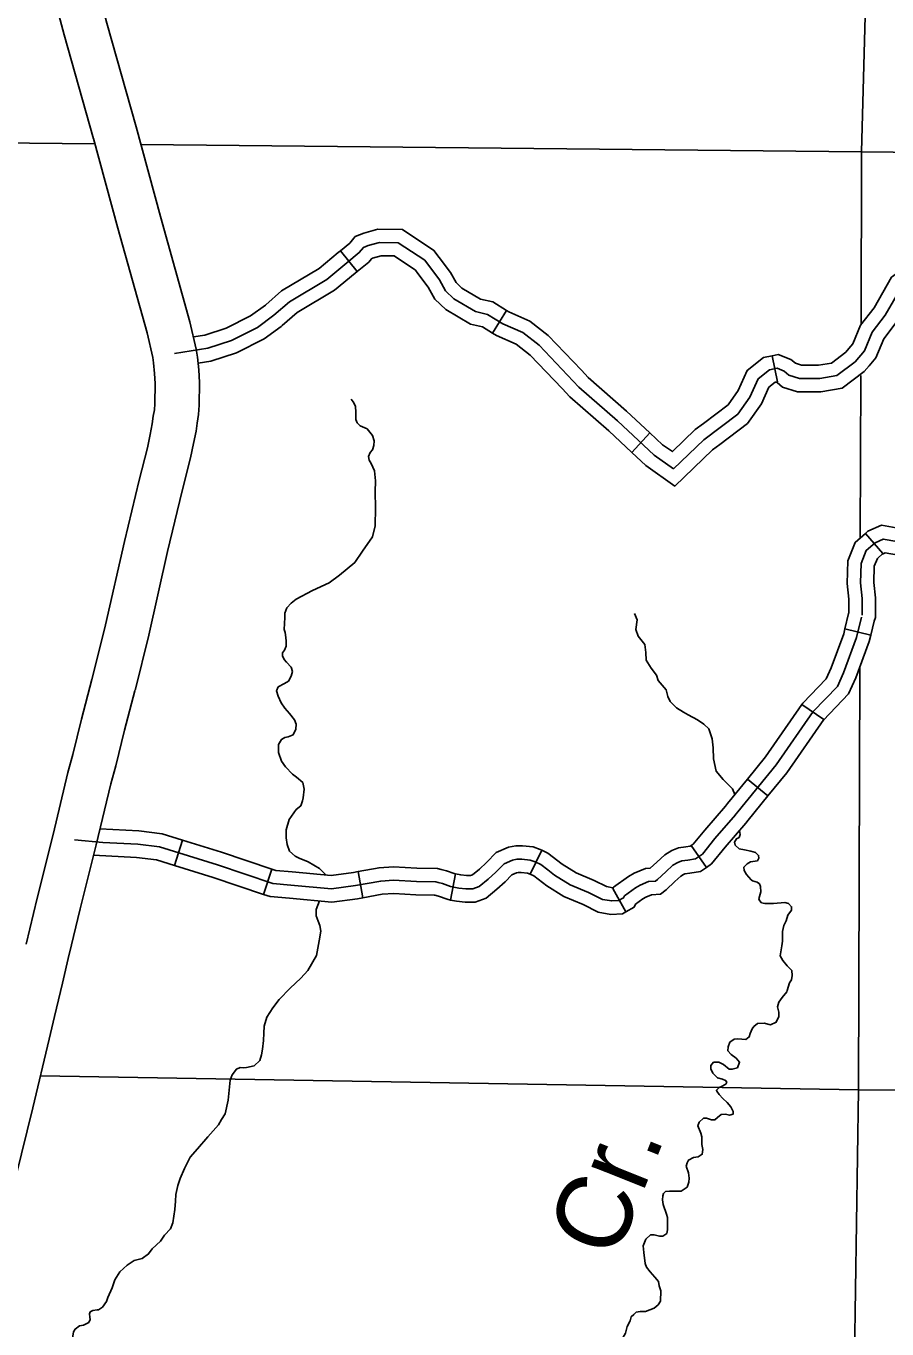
# Model space of a CAD drawing. Extents: x 8749 to 11879, y 13275 to 15339.
# Drawn here: x 10331.7 to 10428.7, y 14052.6 to 14199.4 of the extents above; entities that cross this region are included whole.
import ezdxf

# ---------------------------------------------------------------- set-up
doc = ezdxf.new("R2010")
doc.units = 0
for name, color, linetype in [('Level 10', 7, 'Continuous'), ('Level 31', 7, 'Continuous'), ('Level 32', 7, 'Continuous'), ('Level 35', 7, 'Continuous'), ('Level 45', 7, 'Continuous'), ('Level 5', 7, 'Continuous')]:
    doc.layers.add(name, color=color, linetype=linetype)

msp = doc.modelspace()

# ---------------------------------------------------------------- linework, layer by layer
at = {"layer": 'Level 10'}
msp.add_line((10344.08, 14188.03), (10344.08, 14188.05), dxfattribs=at)
for points in [[(10344.08, 14188.05), (10340.79, 14199.71), (10338.28, 14209.16), (10335.38, 14217.79), (10332.16, 14227.56)], [(10327.41, 14225.99), (10330.64, 14216.21), (10333.49, 14207.73), (10335.96, 14198.39), (10339.26, 14186.69)], [(10351.12, 14155.6), (10351.17, 14156.65), (10351.23, 14159.22), (10351.14, 14160.66), (10350.99, 14162.06), (10350.86, 14162.97), (10350.14, 14166.05), (10346.84, 14177.94), (10344.08, 14188.03)], [(10339.26, 14186.71), (10342.02, 14176.61), (10345.3, 14164.81), (10345.94, 14162.04), (10346.03, 14161.45), (10346.15, 14160.25), (10346.22, 14159.12), (10346.17, 14156.82), (10346.14, 14156.15)], [(10346.14, 14156.15), (10346.01, 14155.42), (10345.9, 14154.58), (10345.65, 14153.35), (10345.34, 14151.85), (10344.42, 14148.22), (10342.75, 14141.32), (10340.63, 14131.91), (10339.09, 14125.72)], [(10343.95, 14124.52), (10345.49, 14130.76), (10347.62, 14140.18), (10349.28, 14147.02), (10350.21, 14150.74), (10350.54, 14152.35), (10350.83, 14153.74), (10350.95, 14154.65), (10351.12, 14155.6)], [(10339.1, 14125.75), (10337.93, 14121.29), (10336.93, 14117.31), (10336.37, 14115.26), (10334.71, 14108.29), (10332.92, 14101.11), (10331.67, 14095.93)], [(10336.53, 14094.76), (10337.77, 14099.92), (10339.57, 14107.11), (10341.21, 14114.01), (10341.77, 14116.03), (10342.78, 14120.05), (10343.94, 14124.49)], [(10323.8, 14042.22), (10325.15, 14048.05), (10326.75, 14054.38), (10328.56, 14061.5), (10329.05, 14063.5), (10330.13, 14068.11), (10330.53, 14069.71), (10332.43, 14077.47), (10334.26, 14085.21), (10334.89, 14087.78), (10335.79, 14091.54), (10336.54, 14094.78)]]:
    msp.add_lwpolyline(points, dxfattribs=at)
at = {"layer": 'Level 31'}
for points in [[(10431.13, 14141.08), (10428.29, 14141.58), (10427.38, 14141.17), (10426.37, 14140.3), (10425.78, 14138.83), (10425.73, 14136.63), (10425.91, 14134.89), (10425.9, 14133)], [(10425.82, 14132.76), (10425.27, 14130.47), (10423.81, 14126.5), (10423.12, 14124.97), (10420.37, 14122.13), (10416.22, 14116.14), (10411.89, 14110.83), (10411.53, 14110.38)], [(10411.64, 14110.51), (10409.31, 14107.82), (10407.9, 14106.08), (10407.12, 14105.54), (10406.25, 14105.4), (10405.57, 14105.31), (10405.12, 14105.14), (10404.57, 14104.81), (10403.79, 14104.07), (10402.83, 14103.21), (10402.6, 14103.02), (10401.83, 14102.98), (10400.87, 14102.57), (10400.37, 14102.29), (10399.11, 14101.37), (10399.02, 14101.14), (10398.45, 14100.83), (10397.68, 14100.79), (10396.63, 14100.97), (10395.07, 14101.75), (10392.98, 14102.61), (10391.24, 14103.71), (10390.47, 14104.3), (10389.69, 14104.9), (10389.05, 14105.22), (10388.5, 14105.4), (10387.55, 14105.49), (10387, 14105.49), (10386.5, 14105.4), (10385.54, 14104.99), (10384.63, 14104.03), (10383.76, 14103.25), (10382.75, 14102.43), (10382.02, 14102.16), (10381.25, 14102.16), (10380.43, 14102.25), (10379.51, 14102.43), (10378.6, 14102.75), (10378.1, 14102.89)], [(10378.1, 14102.89), (10377.86, 14102.95), (10375.66, 14102.99), (10373.1, 14103.13), (10371.64, 14103.04), (10368.8, 14102.53), (10366.1, 14102.17), (10361.52, 14102.58), (10359.5, 14102.76), (10353.23, 14104.87), (10346.69, 14106.89), (10344.26, 14107.21), (10340.32, 14107.39), (10337.14, 14107.7)]]:
    msp.add_lwpolyline(points, dxfattribs=at)
at = {"layer": 'Level 32'}
for p, q in [((10426.29, 14142.21), (10428.25, 14139.94)), ((10423.97, 14131.46), (10426.89, 14130.76)), ((10419.12, 14122.95), (10421.58, 14121.24)), ((10412.97, 14114.52), (10415.29, 14112.63)), ((10349.3, 14107.65), (10348.41, 14104.79)), ((10389.82, 14106.51), (10388.48, 14103.82)), ((10406.64, 14107.04), (10408.37, 14104.58)), ((10359.38, 14104.39), (10358.42, 14101.54)), ((10369.11, 14104.11), (10369.63, 14101.16)), ((10380.09, 14103.84), (10379.5, 14100.9)), ((10397.82, 14102.2), (10399.26, 14099.57))]:
    msp.add_line(p, q, dxfattribs=at)
for points in [[(10437.69, 14141.8), (10434.69, 14141.97), (10431.39, 14142.55), (10428.1, 14143.14), (10426.56, 14142.45), (10426.29, 14142.21)], [(10426.29, 14142.21), (10425.12, 14141.2), (10424.28, 14139.14), (10424.23, 14136.57), (10424.41, 14134.81), (10424.41, 14133.25), (10424.38, 14133.18), (10423.97, 14131.46)], [(10437.52, 14138.8), (10434.35, 14138.99), (10430.87, 14139.6), (10428.49, 14140.02), (10428.19, 14139.89), (10428.25, 14139.94)], [(10428.25, 14139.94), (10427.63, 14139.4), (10427.27, 14138.52), (10427.23, 14136.69), (10427.41, 14134.96), (10427.4, 14132.74), (10427.26, 14132.34), (10426.89, 14130.76)], [(10423.97, 14131.46), (10423.84, 14130.9), (10422.42, 14127.07), (10421.86, 14125.82), (10419.21, 14123.08), (10419.12, 14122.95)], [(10426.89, 14130.76), (10426.71, 14130.03), (10425.2, 14125.94), (10424.38, 14124.12), (10421.54, 14121.17), (10421.59, 14121.24)], [(10419.12, 14122.95), (10415.02, 14117.05), (10412.97, 14114.52)], [(10421.58, 14121.24), (10417.42, 14115.24), (10415.29, 14112.63)], [(10412.97, 14114.52), (10410.73, 14111.78), (10410.49, 14111.48), (10408.16, 14108.78), (10406.86, 14107.19), (10406.64, 14107.04)], [(10415.29, 14112.63), (10413.06, 14109.89), (10412.79, 14109.55), (10410.46, 14106.86), (10408.93, 14104.98), (10408.37, 14104.58)], [(10349.3, 14107.65), (10347.01, 14108.36), (10344.39, 14108.7), (10340, 14108.91)], [(10359.38, 14104.39), (10353.69, 14106.3), (10349.3, 14107.65)], [(10389.82, 14106.51), (10389.63, 14106.61), (10388.82, 14106.88), (10387.62, 14106.99), (10386.86, 14106.99), (10386.06, 14106.84), (10384.66, 14106.25), (10383.58, 14105.11), (10382.78, 14104.39), (10382, 14103.75), (10381.75, 14103.66), (10381.33, 14103.66), (10380.66, 14103.73), (10380.09, 14103.84)], [(10397.82, 14102.28), (10397.1, 14102.41), (10395.7, 14103.11), (10393.67, 14103.95), (10392.1, 14104.94), (10390.49, 14106.17), (10389.82, 14106.51)], [(10406.64, 14107.04), (10406.54, 14106.96), (10406.04, 14106.88), (10405.2, 14106.77), (10404.47, 14106.49), (10403.66, 14106.01), (10402.77, 14105.18), (10402.02, 14104.49), (10401.48, 14104.46), (10400.21, 14103.92), (10399.56, 14103.56), (10397.88, 14102.33), (10397.83, 14102.2), (10397.82, 14102.2)], [(10348.41, 14104.79), (10346.37, 14105.42), (10344.13, 14105.71), (10339.28, 14105.94)], [(10358.42, 14101.54), (10352.77, 14103.44), (10348.41, 14104.79)], [(10369.11, 14104.11), (10368.57, 14104.02), (10366.06, 14103.68), (10361.65, 14104.07), (10359.82, 14104.24), (10359.38, 14104.39)], [(10380.09, 14103.84), (10379.91, 14103.88), (10379.05, 14104.18), (10378.47, 14104.34), (10378.05, 14104.44), (10375.72, 14104.49), (10373.09, 14104.63), (10371.46, 14104.53), (10369.11, 14104.11)], [(10388.48, 14103.82), (10388.48, 14103.83), (10388.19, 14103.92), (10387.47, 14103.99), (10387.13, 14103.99), (10386.93, 14103.95), (10386.41, 14103.73), (10385.67, 14102.95), (10384.73, 14102.11), (10383.51, 14101.11), (10382.3, 14100.66), (10381.17, 14100.66), (10380.2, 14100.76), (10379.5, 14100.9)], [(10399.26, 14099.57), (10398.88, 14099.35), (10397.59, 14099.28), (10396.15, 14099.53), (10394.45, 14100.38), (10392.28, 14101.28), (10390.38, 14102.48), (10388.89, 14103.62), (10388.48, 14103.82)], [(10408.37, 14104.58), (10407.7, 14104.11), (10406.47, 14103.91), (10405.94, 14103.84), (10405.78, 14103.78), (10405.47, 14103.6), (10404.81, 14102.97), (10403.8, 14102.06), (10403.17, 14101.55), (10402.18, 14101.5), (10401.53, 14101.22), (10401.17, 14101.02), (10400.35, 14100.42), (10400.21, 14100.09), (10399.26, 14099.57)], [(10369.63, 14101.16), (10369.03, 14101.05), (10366.13, 14100.66), (10361.38, 14101.09), (10359.19, 14101.29), (10358.42, 14101.54)], [(10379.5, 14100.9), (10379.12, 14100.98), (10378.15, 14101.32), (10377.73, 14101.44), (10377.67, 14101.45), (10375.61, 14101.49), (10373.11, 14101.63), (10371.81, 14101.55), (10369.63, 14101.16)]]:
    msp.add_lwpolyline(points, dxfattribs=at)
at = {"layer": 'Level 35'}
for points in [[(10370.11, 14153.99), (10369.33, 14154.34), (10368.97, 14154.67), (10368.82, 14155.05), (10368.82, 14155.84), (10368.79, 14156.55), (10368.52, 14157.06), (10368.31, 14157.36)], [(10370.93, 14149.25), (10370.57, 14150.1), (10370.34, 14150.48), (10370.27, 14150.89), (10370.47, 14151.32), (10370.72, 14151.62), (10370.88, 14152.13), (10370.9, 14152.64), (10370.7, 14153.25), (10370.11, 14153.99)], [(10368.72, 14138.92), (10369.58, 14140.21), (10370.7, 14141.84), (10371, 14143.06), (10371.05, 14145.09), (10371.03, 14146.89), (10371.05, 14148.16), (10370.93, 14149.25)], [(10362.12, 14134.79), (10363.95, 14135.79), (10365.83, 14136.63), (10366.99, 14137.52), (10368.72, 14138.92)], [(10360.07, 14124.94), (10360.78, 14125.29), (10361.23, 14125.57), (10361.54, 14126.11), (10361.69, 14126.66), (10361.56, 14127.15), (10361.03, 14127.71), (10360.75, 14128.01), (10360.57, 14128.42), (10360.57, 14128.75), (10360.8, 14129.05), (10360.98, 14129.51), (10360.98, 14130.09), (10360.93, 14130.47), (10360.88, 14131.03), (10360.75, 14131.39), (10360.78, 14132.07), (10360.85, 14132.73), (10360.83, 14133.22), (10361.05, 14133.83), (10361.56, 14134.36), (10362.12, 14134.79)], [(10405.77, 14122.08), (10405, 14122.56), (10404.25, 14123.26), (10404.02, 14123.84), (10403.8, 14124.59), (10403.35, 14125.11), (10402.92, 14125.64), (10402.72, 14126.24), (10402.13, 14127.04), (10401.58, 14127.94), (10401.53, 14128.81), (10401.4, 14129.71), (10400.68, 14130.64), (10400.4, 14131.38), (10400.53, 14132.48), (10400.25, 14133.18)], [(10360.14, 14118.43), (10360.45, 14119), (10360.83, 14119.2), (10361.21, 14119.28), (10361.77, 14119.53), (10362.07, 14120.14), (10362.1, 14120.7), (10361.94, 14121.19), (10361.38, 14121.92), (10360.85, 14122.53), (10360.42, 14123.12), (10360.07, 14123.88), (10359.91, 14124.46), (10360.07, 14124.94)], [(10411.28, 14113.44), (10410.23, 14114.48), (10409.44, 14115.43), (10409.14, 14116.8), (10409.11, 14118.05), (10409.01, 14119.05), (10408.64, 14120.18), (10408.06, 14120.73), (10407.36, 14121.2), (10406.31, 14121.78), (10405.77, 14122.08)], [(10364.76, 14104.44), (10363.47, 14105.22), (10362.45, 14105.61), (10361.99, 14105.86), (10361.38, 14106.42), (10361.08, 14107.16), (10361, 14107.92), (10360.98, 14108.81), (10361.33, 14109.97), (10362.12, 14111.12), (10362.65, 14111.52), (10362.83, 14112.06), (10362.91, 14112.41), (10363.03, 14113.4), (10362.88, 14114.14), (10362.15, 14114.75), (10361.71, 14115.1), (10360.9, 14115.92), (10360.45, 14116.53), (10360.14, 14117.52), (10360.14, 14118.43)], [(10411.57, 14112.81), (10411.28, 14113.44)], [(10413.38, 14103.16), (10412.88, 14103.77), (10412.61, 14104.22), (10412.56, 14104.6), (10412.93, 14104.97), (10413.33, 14105.2), (10414.1, 14105.3), (10414.28, 14105.62), (10414.23, 14105.92), (10413.9, 14106.25), (10413.36, 14106.42), (10412.66, 14106.55), (10412.03, 14106.67), (10411.61, 14107.1), (10411.51, 14107.42), (10411.76, 14107.8), (10412.03, 14107.95), (10412.16, 14108.3), (10412.09, 14108.75)], [(10365.46, 14103.73), (10364.76, 14104.44)], [(10416.93, 14096.27), (10416.93, 14097.36), (10417.08, 14098.01), (10417.35, 14098.56), (10417.52, 14099.21), (10417.95, 14099.76), (10417.95, 14100.14), (10417.62, 14100.49), (10417.18, 14100.61), (10415.93, 14100.51), (10415.43, 14100.49), (10414.95, 14100.51), (10414.58, 14100.59), (10414.33, 14100.84), (10414.28, 14101.04), (10414.48, 14101.81), (10414.45, 14102.41), (10414.35, 14102.71), (10414.08, 14102.93), (10413.55, 14103.08), (10413.38, 14103.16)], [(10360.2, 14089.69), (10361.44, 14090.95), (10362.63, 14092.09), (10363.44, 14092.95), (10364.4, 14094.63), (10364.71, 14096.31), (10364.91, 14097.4), (10364.79, 14098.03), (10364.58, 14098.52), (10364.35, 14099.13), (10364.35, 14099.84), (10364.73, 14100.79)], [(10410.99, 14084.87), (10411.48, 14085.2), (10411.91, 14085.25), (10412.78, 14085.18), (10413.18, 14085.48), (10413.28, 14085.85), (10413.5, 14086.4), (10413.68, 14086.63), (10414.13, 14086.98), (10414.88, 14087.03), (10415.58, 14086.83), (10416.23, 14087.13), (10416.5, 14087.78), (10416.53, 14088.25), (10416.38, 14088.88), (10416.53, 14089.4), (10416.9, 14089.9), (10417.42, 14090.57), (10417.47, 14090.7), (10417.72, 14091.55), (10417.95, 14091.92), (10418.02, 14092.4), (10418, 14092.95), (10417.45, 14093.5), (10416.95, 14094.1), (10416.68, 14094.62), (10416.85, 14095.75), (10416.93, 14096.27)], [(10356.52, 14082.01), (10357.38, 14082.22), (10358.01, 14082.83), (10358.22, 14083.47), (10358.32, 14084.1), (10358.42, 14085.07), (10358.45, 14085.88), (10358.5, 14086.67), (10358.8, 14087.7), (10359.49, 14088.75), (10360.2, 14089.69)], [(10407.72, 14074.62), (10407.39, 14075.45), (10407.52, 14075.87), (10408.04, 14076.3), (10408.37, 14076.3), (10408.94, 14076.12), (10409.29, 14076.12), (10409.62, 14076.4), (10410.01, 14076.72), (10410.51, 14076.75), (10410.96, 14076.65), (10411.36, 14076.77), (10411.36, 14077.05), (10411.09, 14077.6), (10410.69, 14078.07), (10410.19, 14078.55), (10409.79, 14078.97), (10409.52, 14079.37), (10409.49, 14079.47), (10409.79, 14079.77), (10410.04, 14079.87), (10410.54, 14080.15), (10410.64, 14080.37), (10410.51, 14080.55), (10410.16, 14080.7), (10409.62, 14080.85), (10409.09, 14081.37), (10408.84, 14081.87), (10408.84, 14082.25), (10409.17, 14082.62), (10409.76, 14082.62), (10410.29, 14082.37), (10410.91, 14081.85), (10411.26, 14081.82), (10411.84, 14082), (10412.09, 14082.62), (10411.69, 14083.09), (10411.16, 14083.49), (10410.76, 14083.92), (10410.79, 14084.34), (10410.99, 14084.87)], [(10349.52, 14070.65), (10350.17, 14071.92), (10351.01, 14072.86), (10352.15, 14074.21), (10353.37, 14075.58), (10353.7, 14076.17), (10354.11, 14076.8), (10354.44, 14078.35), (10354.56, 14079.47), (10354.69, 14080.61), (10354.89, 14081.2), (10355.38, 14081.83), (10355.81, 14082.01), (10356.19, 14081.98), (10356.52, 14082.01)], [(10403.87, 14065.48), (10403.47, 14066.6), (10403.42, 14067.12), (10403.45, 14067.55), (10403.52, 14067.82), (10403.75, 14068.05), (10404.2, 14068.1), (10404.87, 14068.1), (10405.49, 14068.07), (10406.17, 14068.55), (10406.39, 14069.12), (10406.42, 14069.57), (10406.34, 14070.14), (10406.07, 14070.89), (10406.17, 14071.27), (10406.34, 14071.59), (10406.89, 14071.87), (10407.42, 14071.94), (10407.89, 14072.24), (10407.94, 14072.77), (10407.84, 14073.34), (10407.82, 14074.22), (10407.72, 14074.62)], [(10341.68, 14058.11), (10342.24, 14058.99), (10343.07, 14059.73), (10343.86, 14060.26), (10344.77, 14060.49), (10345.48, 14061.02), (10345.89, 14061.58), (10346.83, 14062.44), (10347.29, 14063.13), (10347.95, 14063.84), (10348.23, 14064.53), (10348.45, 14066.02), (10348.5, 14066.96), (10348.55, 14067.73), (10348.76, 14068.74), (10349.04, 14069.53), (10349.52, 14070.65)], [(10401.53, 14062.69), (10402.05, 14063.15), (10402.47, 14063.15), (10403.05, 14063.03), (10403.45, 14063.03), (10403.9, 14063.33), (10403.97, 14063.73), (10403.95, 14064.23), (10403.95, 14065.13), (10403.87, 14065.48)], [(10398.16, 14050.2), (10399.23, 14052.09), (10399.43, 14052.84), (10399.75, 14053.49), (10399.88, 14053.94), (10400.18, 14054.19), (10400.45, 14054.47), (10400.9, 14054.52), (10401.5, 14054.54), (10402.45, 14054.89), (10402.9, 14055.27), (10403.17, 14055.69), (10403.2, 14056.84), (10403.02, 14057.42), (10402.95, 14057.89), (10402.55, 14058.39), (10402.02, 14058.99), (10401.6, 14059.52), (10401.45, 14059.94), (10401.3, 14061.19), (10401.23, 14061.92), (10401.53, 14062.69)], [(10337.52, 14050.48), (10337.39, 14050.87), (10337.06, 14051.26), (10336.93, 14051.74), (10337.03, 14052.22), (10337.19, 14052.55), (10337.69, 14052.91), (10338.15, 14052.98), (10338.76, 14053.29), (10338.91, 14053.64), (10338.86, 14053.87), (10338.81, 14054.28), (10338.91, 14054.48), (10339.19, 14054.63), (10339.67, 14054.71), (10339.83, 14054.73), (10340.28, 14055.01), (10340.74, 14055.65), (10340.87, 14056.11), (10341.37, 14057.2), (10341.68, 14058.11)]]:
    msp.add_lwpolyline(points, dxfattribs=at)
at = {"layer": 'Level 45'}
for p, q in [((10367.11, 14174.08), (10368.99, 14171.75)), ((10385.82, 14167.34), (10384.24, 14164.8)), ((10415.75, 14162.24), (10416.36, 14159.31)), ((10401.99, 14153.54), (10399.94, 14151.35))]:
    msp.add_line(p, q, dxfattribs=at)
for points in [[(10378.23, 14173.31), (10377.64, 14174.1), (10374.09, 14176.46), (10371.32, 14176.52), (10369.74, 14176.06), (10368.77, 14175.66), (10368.17, 14174.94), (10367.11, 14174.08)], [(10404.66, 14149.49), (10402.46, 14151.05), (10398.34, 14154.9), (10393.99, 14158.7), (10389.51, 14163.42), (10387.68, 14164.84), (10385.39, 14165.85), (10383.69, 14166.9), (10382.32, 14167.22), (10379.89, 14168.64), (10378.93, 14169.56), (10378.25, 14170.8), (10376.6, 14173), (10373.62, 14174.97), (10371.52, 14175.01), (10370.23, 14174.65), (10369.69, 14174.42), (10369.23, 14173.87), (10367.81, 14172.72), (10365.57, 14170.84), (10361.35, 14168.32), (10359.61, 14166.81), (10357.74, 14165.43), (10354.81, 14163.97), (10352.15, 14163.1), (10348.4, 14162.5)], [(10367.11, 14174.08), (10366.86, 14173.88), (10364.69, 14172.07), (10360.47, 14169.54), (10358.68, 14167.98), (10358.64, 14167.95)], [(10375.83, 14171.52), (10375.55, 14171.89), (10373.16, 14173.48), (10371.71, 14173.51), (10370.73, 14173.23), (10370.6, 14173.17), (10370.29, 14172.79), (10368.99, 14171.75)], [(10385.82, 14167.34), (10384.28, 14168.31), (10382.88, 14168.63), (10380.8, 14169.85), (10380.13, 14170.49), (10379.51, 14171.61), (10378.23, 14173.31)], [(10368.99, 14171.75), (10368.76, 14171.56), (10366.44, 14169.62), (10362.24, 14167.1), (10360.55, 14165.64), (10360.41, 14165.53)], [(10384.24, 14164.8), (10383.11, 14165.5), (10381.76, 14165.81), (10378.99, 14167.44), (10377.73, 14168.63), (10376.98, 14169.98), (10375.83, 14171.52)], [(10430.43, 14171.96), (10429.23, 14171.08), (10427.25, 14167.64), (10425.72, 14165.67), (10424.86, 14163.59), (10424.4, 14163.04)], [(10430.37, 14170.06), (10428.5, 14166.81), (10427.03, 14164.91), (10426.16, 14162.8), (10425.11, 14161.56), (10423.05, 14160), (10421.13, 14159.68), (10418.84, 14159.68), (10417.65, 14160.05), (10417.1, 14160.51), (10416.32, 14160.83), (10415.45, 14160.65), (10414.17, 14159.64), (10413.25, 14157.58), (10411.88, 14155.65), (10408.08, 14152.77), (10404.66, 14149.49)], [(10432.2, 14169.54), (10431.51, 14169.03), (10429.74, 14165.97), (10428.34, 14164.15), (10427.46, 14162.01), (10426.68, 14161.1)], [(10358.64, 14167.95), (10356.95, 14166.72), (10354.24, 14165.36), (10351.8, 14164.56), (10350.54, 14164.36)], [(10394.26, 14160.6), (10390.52, 14164.53), (10388.45, 14166.14), (10386.09, 14167.18), (10385.82, 14167.34)], [(10360.41, 14165.53), (10358.52, 14164.15), (10355.38, 14162.58), (10352.51, 14161.64), (10351.06, 14161.41)], [(10392.08, 14158.53), (10388.5, 14162.3), (10386.9, 14163.54), (10384.68, 14164.52), (10384.24, 14164.8)], [(10415.75, 14162.24), (10414.8, 14162.04), (10412.95, 14160.59), (10411.94, 14158.32), (10410.79, 14156.71), (10408.03, 14154.61)], [(10424.4, 14163.04), (10424.07, 14162.66), (10422.44, 14161.42), (10421, 14161.18), (10419.06, 14161.18), (10418.38, 14161.4), (10417.88, 14161.81), (10416.46, 14162.39), (10415.75, 14162.24)], [(10401.99, 14153.54), (10399.35, 14156.01), (10395.03, 14159.78), (10394.26, 14160.6)], [(10426.68, 14161.1), (10426.14, 14160.47), (10423.66, 14158.59), (10421.25, 14158.18), (10418.61, 14158.18), (10416.92, 14158.71), (10416.31, 14159.21), (10416.18, 14159.27), (10416.36, 14159.31)], [(10416.36, 14159.31), (10416.1, 14159.25), (10415.39, 14158.69), (10414.56, 14156.83), (10412.97, 14154.6), (10409.85, 14152.23)], [(10399.94, 14151.35), (10397.34, 14153.78), (10392.95, 14157.62), (10392.08, 14158.53)], [(10408.03, 14154.61), (10407.1, 14153.91), (10404.52, 14151.43), (10403.41, 14152.21), (10401.99, 14153.54)], [(10409.85, 14152.23), (10409.05, 14151.62), (10404.8, 14147.55), (10401.51, 14149.88), (10399.94, 14151.35)]]:
    msp.add_lwpolyline(points, dxfattribs=at)
at = {"layer": 'Level 5'}
for points in [[(10428.7, 14290.86), (10425.85, 14185.23)], [(10317.26, 14186.34), (10339.42, 14186.11)], [(10344.62, 14186.06), (10425.85, 14185.23)], [(10425.85, 14185.23), (10425.78, 14165.74)], [(10425.85, 14185.23), (10532.75, 14184.09)], [(10425.76, 14160.01), (10425.69, 14141.69)], [(10425.64, 14127.14), (10425.48, 14079.51)], [(10333.28, 14081.07), (10425.48, 14079.51)], [(10425.48, 14079.51), (10424.58, 14019.39)], [(10425.48, 14079.51), (10486.76, 14078.97)]]:
    msp.add_lwpolyline(points, dxfattribs=at)

# ---------------------------------------------------------------- texts
at = {"layer": 'Level 35'}
msp.add_text('Cr.', height=8.448, rotation=68.217, dxfattribs=at).set_placement((10398.1, 14060.16))

doc.saveas('drawing.dxf')
